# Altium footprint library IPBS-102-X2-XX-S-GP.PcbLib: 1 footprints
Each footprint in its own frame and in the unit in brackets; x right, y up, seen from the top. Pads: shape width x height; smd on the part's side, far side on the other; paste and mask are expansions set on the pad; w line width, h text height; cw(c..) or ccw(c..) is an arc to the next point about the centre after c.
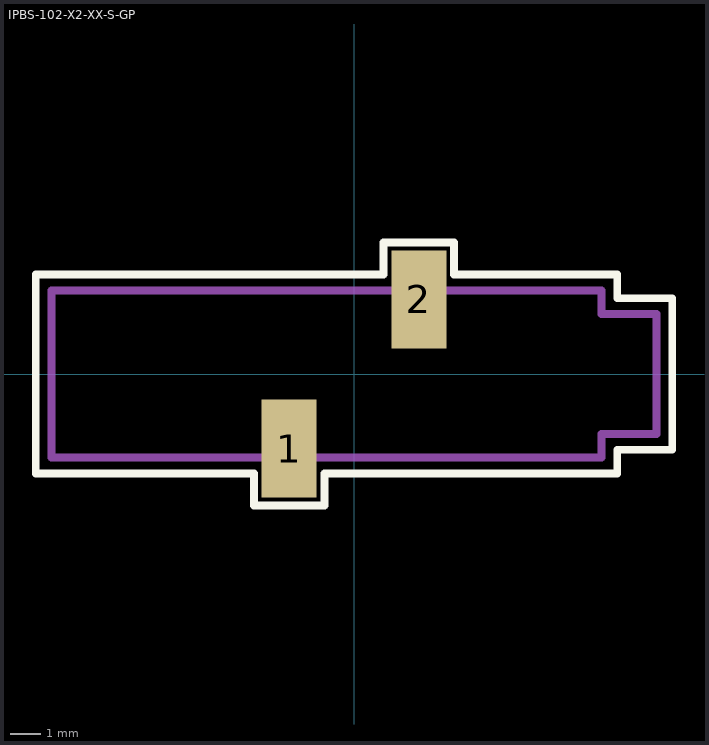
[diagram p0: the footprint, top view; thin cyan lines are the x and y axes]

## IPBS-102-X2-XX-S-GP [mil]
pads (2):
  rect 70x125 smd mask+2: 1(-82.5,-95) 2(82.5,95)
Top Overlay:
  lines w10: -405,-126.5 -405,126.5 37.5,126.5 37.5,167.5 127.5,167.5 127.5,126.5 335,126.5 335,96.5 405,96.5 405,-96.5 335,-96.5 335,-126.5 -37.5,-126.5 -37.5,-167.5 -127.5,-167.5 -127.5,-126.5 -405,-126.5
Mechanical 1:
  lines w10: -385,-106.5 -385,106.5 315,106.5 315,76.5 385,76.5 385,-76.5 315,-76.5 315,-106.5 -385,-106.5
  text "J1" at -23.42,-24 h40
